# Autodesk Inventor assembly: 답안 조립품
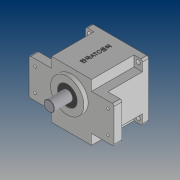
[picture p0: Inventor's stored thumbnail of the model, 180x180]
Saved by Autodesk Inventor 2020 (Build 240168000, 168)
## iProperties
Created: 2020-07
Part Number: 답안 조립품
Document SubType Name: Assembly
Designer: PC312-
Author: PC312-
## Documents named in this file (10)
- C:\Users\PC312-\Desktop\700718V1012\답안 조립품.iam
- C:\Users\PC312-\Desktop\700718V1012\1.본체.ipt
- C:\Users\PC312-\Desktop\700718V1012\베어링 6003.ipt
- C:\Users\PC312-\Desktop\700718V1012\베어링 608.ipt
- C:\Users\PC312-\Desktop\700718V1012\커버.ipt
- C:\Users\PC312-\Desktop\700718V1012\메인 축.ipt
- C:\Users\PC312-\Desktop\700718V1012\오일 실 8 22 7.ipt
- C:\Users\PC312-\Desktop\700718V1012\서브 축.ipt
- C:\Users\PC312-\Desktop\700718V1012\오일 실 17 32 8.ipt
- C:\Users\PC312-\Desktop\700718V1012\볼트 M4.ipt
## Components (1 placed, 1 different names)
1. 1.본체:1
